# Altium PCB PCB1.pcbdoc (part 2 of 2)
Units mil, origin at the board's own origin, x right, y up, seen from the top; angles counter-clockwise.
Board outline 2441 x 2440.7 mil, 2 copper layers (Top Layer, Bottom Layer), stack 62.2 mil thick; 65 components, 50 nets, 327 pads, 148 vias.
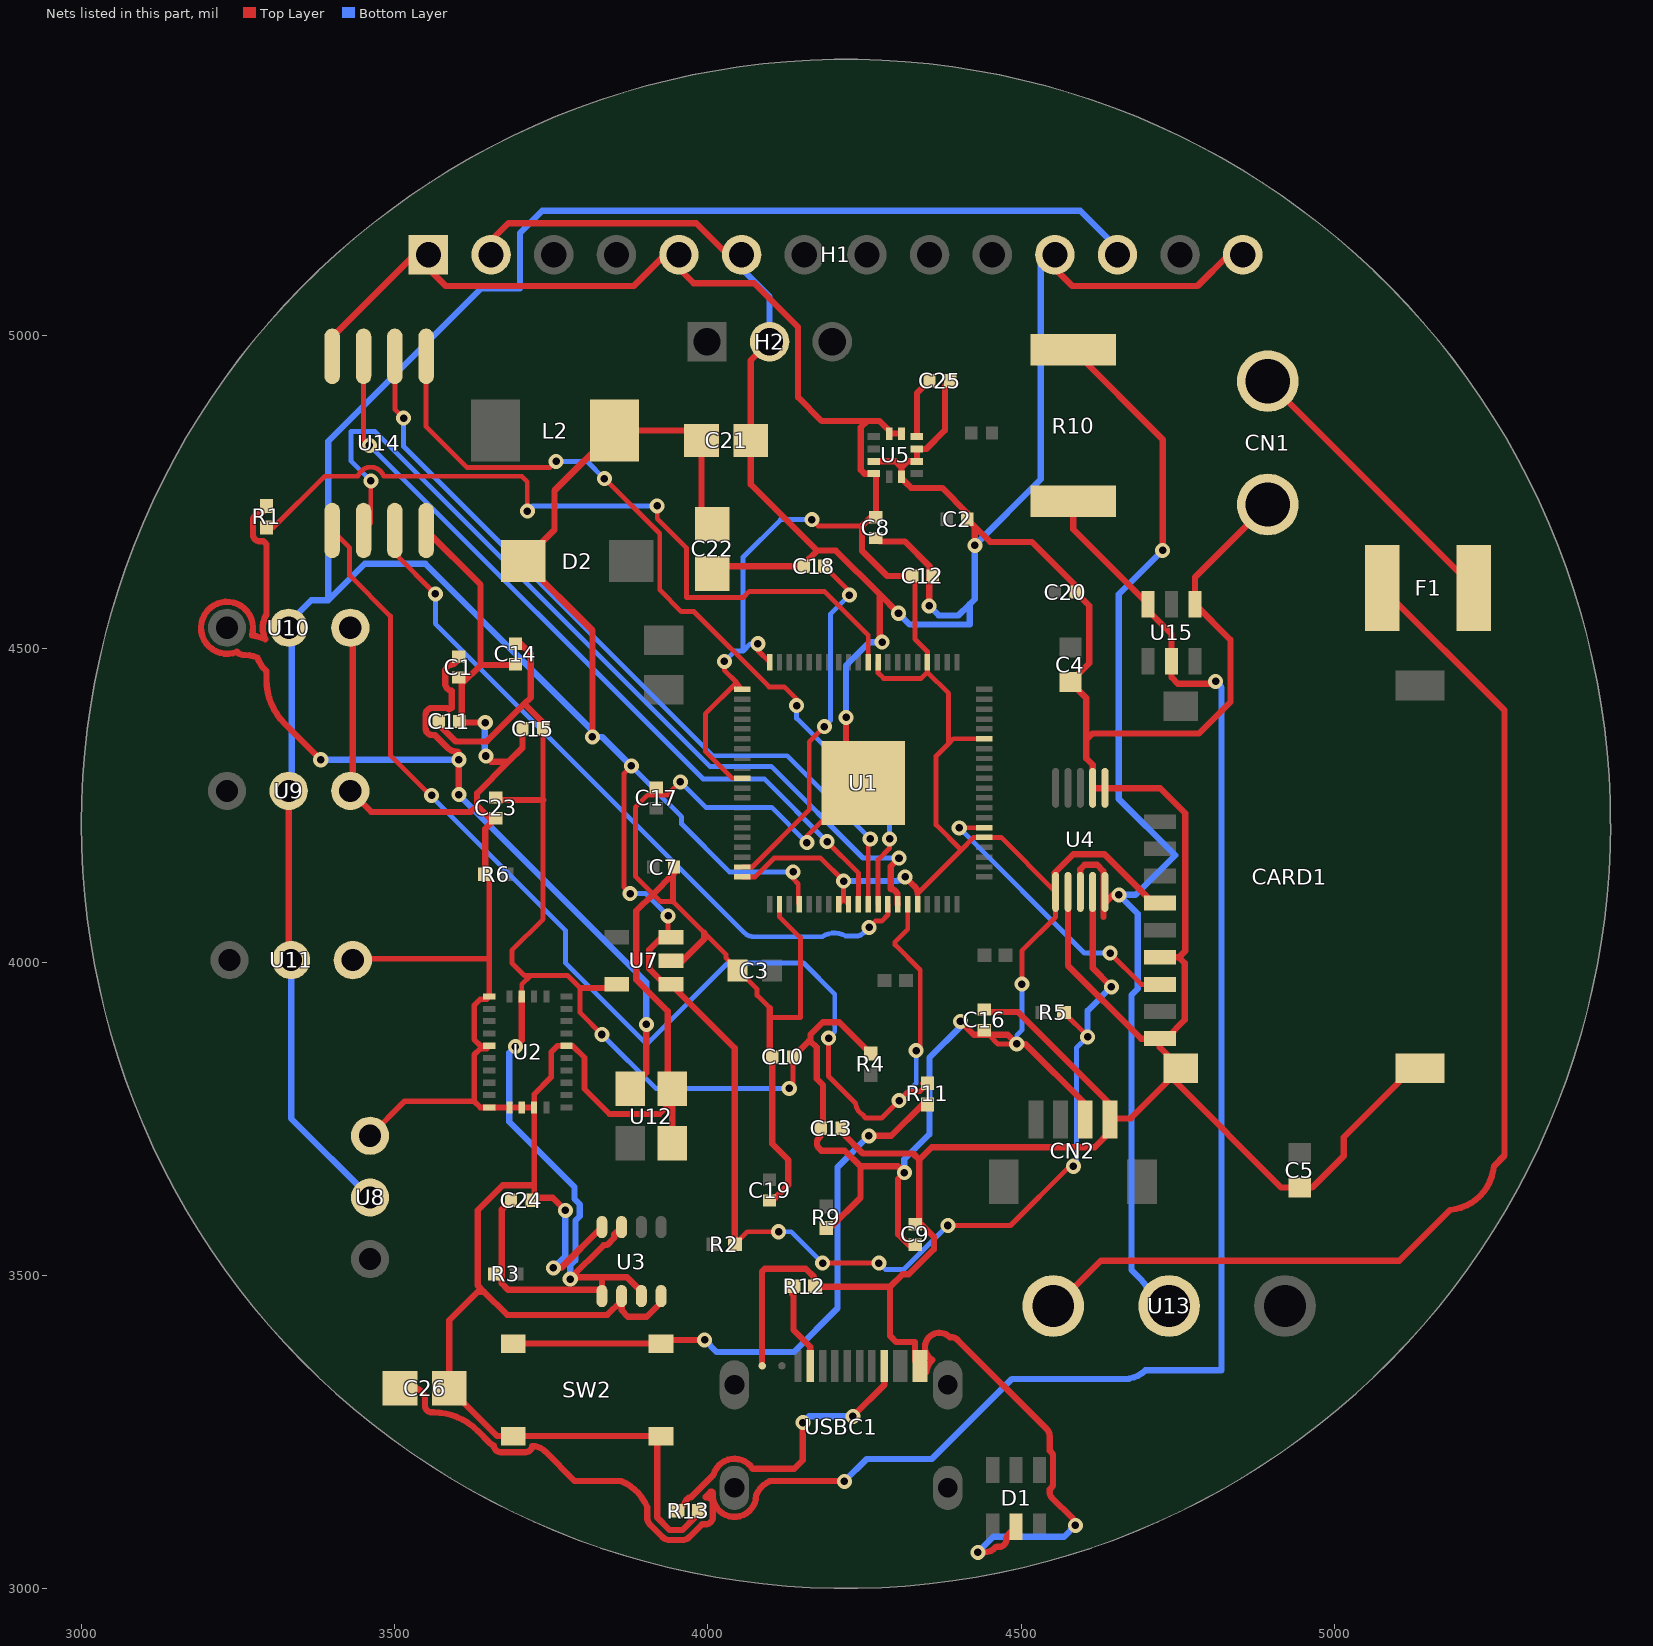
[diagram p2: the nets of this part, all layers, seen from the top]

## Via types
v1: diameter 24, hole 12, Top Layer to Bottom Layer, 148 vias

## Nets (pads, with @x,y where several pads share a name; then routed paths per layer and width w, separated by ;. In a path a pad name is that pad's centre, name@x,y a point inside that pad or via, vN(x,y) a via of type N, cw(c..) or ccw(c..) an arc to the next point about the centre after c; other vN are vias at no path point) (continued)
$1N424: R1.1 U1.30 | length 1256
  Top Layer w7.8: R1.1@3295.4,4693.7 3306.4,4693.7 3388.2,4775.5 3441.3,4775.5 cw(c3461.9,4768.1) 3482.51,4775.52 3703,4775.5 3711.7,4766.8 v1(3711.7,4719.9) ; v1(3919.1,4728.2) 3919.1,4707.6 3966,4660.7 3966,4581.8 4056,4581.8 4066,4591.8 4186,4591.8 4256,4521.8 U1.30@4256,4478.8
  Bottom Layer w7.8: v1(3711.7,4719.9) 3720,4728.2 v1(3919.1,4728.2)
$1N425: C1.1 R1.2 U12.1 | length 1850.3
  Top Layer w10: 3248.1,4495.2 3248.6,4494.7 ccw(c3259.9,4506) 3259.9,4490 3261.9,4490 cw(c3261.9,4444.2) 3280.89,4485.88 ; 3248.15,4495.2 cw(c3232.4,4533.6) 3216.65,4572 cw(c3232.4,4533.6) 3272.07,4521.4 ; 3272.05,4521.33 cw(c3261.9,4444.2) 3293.54,4515.27 ; 3280.84,4485.86 ccw(c3334.7,4506) 3295.34,4464.08 ; 3284.7,4715.8 ccw(c3284.7,4704.8) 3273.7,4704.8 3273.7,4682.6 ccw(c3284.7,4682.6) 3284.7,4671.6 3290,4671.6 ; 3284.7,4715.89 ccw(c3277.2,4734) R1.2@3295.31,4726.5 ; 3290.05,4671.55 cw(c3286.3,4662.5) 3295.35,4666.25 ; 3293.53,4515.34 cw(c3330.8,4533.6) 3295.38,4555.22 3295.4,4666.3 ; 3295.4,4464.1 3295.4,4450.9 ccw(c3395.4,4450.9) 3324.69,4380.19 ; R1.2@3295.4,4726.5 R1.2@3295.4,4727.8 ; 3324.6,4380.2 v1(3382,4322.9) ; 3562.3,4362.3 3560.3,4362.3 cw(c3560.3,4373.3) 3549.3,4373.3 3549.3,4394.6 cw(c3560.3,4394.6) 3560.3,4405.6 3580,4405.6 cw(c3580,4394.6) 3586.7,4403.33 cw(c3593.4,4394.6) 3591.17,4405.37 ; 3562.3,4362.4 cw(c3562.3,4357.6) 3565.69,4360.99 ; 3565.7,4360.9 3585.8,4340.9 ccw(c3597.1,4352.2) 3597.1,4336.2 3599.8,4336.2 ; 3591.15,4433.22 cw(c3591.8,4444.2) 3580.8,4444.2 3580.8,4463.9 cw(c3591.8,4463.9) 3591.8,4474.9 ccw(c3584.3,4493) 3602.41,4485.5 C1.1@3602.4,4487.1 ; 3591.2,4405.4 3591.2,4433.2 ; 3599.78,4336.13 cw(c3597.9,4331.6) v1@3602.43,4333.48 ; v1(3602.4,4267.1) v1@3602.4,4333.5 ; U12.1@3876.1,3797.4 3901.8,3823.1 v1(3901.8,3900.5)
  Bottom Layer w10: v1(3382,4322.9) v1(3602.4,4322.9) ; v1(3602.4,4267.1) 3901.8,3967.8 v1(3901.8,3900.5)
$1N433: C8.1 C9.1 C10.1 C11.1 C12.1 C13.1 C14.1 C15.1 C16.1 C23.1 C24.1 CARD1.4 CN2.2 H1.1 H1.5 R3.2 R4.2 R9.2 U1.5 U1.15 U1.24 U1.29 U1.40 U1.41 U1.50 U1.60 U1.68 U1.69 U1.76 U2.4 U3.2 U3.6 U3.8 U4.6 U5.5 U5.6 U5.10 U7.5 U14.8 | length 8160.8
  Top Layer w7.8: U2.4@3702.8,3945 3702.8,3964.3 3717.1,3978.5 ; C15.1@3737.1,4372.2 3737.1,4258.5 3737.1,4068.5 3687.1,4018.5 3687.1,3998.5 3707.1,3978.5 3717.1,3978.5 ; v1(3830.7,3884.3) 3796,3919 3796,3958.5 3776,3978.5 3717.1,3978.5 ; v1(4026.4,4479.9) 4026.4,4465.9 4046.1,4446.3 ; U1.60@4054.9,4135.9 4075.6,4135.9 4105.6,4165.9 4180,4165.9 v1(4216.6,4129.3) 4216.6,4100.2 ; U1.50@4054.9,4293.4 4038.9,4293.4 3996.1,4336.3 3996.1,4396.3 4046.1,4446.3 ; U1.41@4054.9,4435.2 4046.1,4446.3 ; v1(4080,4508.1) 4080,4497.3 U1.40@4098.5,4478.8 ; v1(4129.9,3798.2) 4136,3804.2 C10.1@4136,3848.5 ; v1(4166.1,4706.3) 4176.1,4696.3 4246.1,4696.3 ; U1.68@4208.7,4092.3 4216.6,4100.2 ; U1.69@4224.5,4092.3 4216.6,4100.2 ; U1.29@4271.7,4478.8 4271.7,4461.5 4280.5,4452.8 4340.5,4452.8 4350.5,4462.8 ; C12.1@4326.1,4616.3 4330.5,4611.8 4330.5,4515.7 4350.5,4495.7 U1.24@4350.5,4478.8 4350.5,4462.8 ; U1.76@4334.7,4092.3 4334.7,4109.3 4404.3,4178.9 ; C16.1@4441,3891.1 4448.3,3883.8 4462.8,3869.2 v1(4493.1,3869.2) ; U1.15@4441.3,4356.4 4391.8,4356.4 4384.3,4348.9 ; v1(4501.3,3964.7) 4501.3,4018 4555.2,4071.9 U4.6@4555.2,4111.9 ; U4.6@4553.2,4113.9 4468.2,4198.9 U1.5@4441.3,4198.9 4424.3,4198.9 4404.3,4178.9 ; 4350.5,4462.8 4384.3,4428.9 4384.3,4348.9 ; 4384.3,4348.9 4364.3,4328.9 4364.3,4218.9 4404.3,4178.9
  Top Layer w8.9: 3796,3958.5 3848.3,3958.5 U7.5@3854.4,3964.7
  Top Layer w9.9: H1.5@3931.6,5129.2 3977.1,5083.6 4074,5083.6 4144,5013.6 4144,4901.7 4182.1,4863.6 4254,4863.6 ; C8.1@4268.2,4710.1 4268.2,4776.2 U5.10@4264.8,4779.6 4250,4779.6 4244,4785.7 4244,4853.6 4254,4863.6 ; U5.5@4309.1,4843.6 U5.6@4289.5,4843.6 4289.5,4848.2 4274,4863.6 4254,4863.6
  Top Layer w10: U14.8@3400.3,4966.9 3400.3,4997.8 3531.6,5129.2 3581.6,5079.2 3881.6,5079.2 H1.5@3931.6,5129.2 ; C11.1@3570.2,4384 3570.2,4379.1 3597.1,4352.2 3647.1,4352.2 3707.1,4412.2 ; R3.2@3660.2,3502.1 3665,3506.9 R3.2@3670.9,3506.9 ; C23.1@3661.5,4262.7 3665.7,4258.5 3737.1,4258.5 ; C24.1@3685.6,3619.7 3670.9,3604.9 R3.2@3670.9,3506.9 ; v1(3692.8,3865) 3702.8,3875 U2.4@3702.8,3945 ; C14.1@3692.8,4508.3 3700.9,4508.3 3717.1,4492.2 3717.1,4422.2 3707.1,4412.2 ; C15.1@3737.1,4372.2 3737.1,4382.2 3707.1,4412.2 ; U3.8@3830.8,3466.7 U3.8@3830.9,3476.9 ; U3.2@3862.3,3576.9 3850.6,3565.2 3850.6,3559.8 3839,3548.2 3833.6,3548.2 3780.3,3494.9 v1(3780.3,3493.9) 3783.3,3496.9 3830.9,3496.9 ; U3.6@3893.8,3466.7 3890.9,3469.5 3890.9,3476.9 3870.9,3496.9 3830.9,3496.9 ; C10.1@4136,3848.5 4161.2,3873.8 4163.7,3873.8 ; 4177.6,3702.5 4181.2,3698.9 4218.6,3698.9 4243.7,3673.8 ; 4177.64,3702.44 cw(c4186.2,3711) 4174.1,3711 4174.1,3711.6 cw(c4184.8,3711.6) 4177.23,3719.17 ccw(c4169.7,3726.7) 4180.4,3726.7 C13.1@4180.4,3734.4 ; C13.1@4183.7,3732.6 4183.7,3803.8 4173.7,3813.8 4173.7,3863.8 4163.7,3873.8 ; R9.2@4189.1,3575.6 4195.6,3575.6 4243.7,3623.8 4243.7,3673.8 ; R4.2@4259.9,3853.8 4209.9,3903.8 4183.7,3903.8 4163.7,3883.8 4163.7,3873.8 ; C8.1@4268.2,4710.1 4259.9,4710.1 4246.1,4696.3 4246.1,4656.3 4286.1,4616.3 C12.1@4326.1,4616.3 ; v1(4315,4135.9) 4329.8,4121.2 ; 4329.81,4121.11 cw(c4318,4109.3) 4334.7,4109.3 ; C9.1@4330.8,3548.5 4320.8,3548.5 4303.7,3565.6 4303.7,3653.8 v1(4313.7,3663.8) 4303.7,3673.8 4243.7,3673.8 ; v1(4403.3,3905.2) 4424.7,3883.8 4448.3,3883.8 4478.6,3883.8 v1(4493.1,3869.2) 4506.9,3869.2 4602.4,3773.7 CN2.2@4602.4,3748.6 ; U4.6@4555.2,4111.9 4553.2,4113.9 4553.2,4141.9 4583.2,4171.9 4633.2,4171.9 4710.9,4094.2 CARD1.4@4721.5,4094.2 ; R3.2@3670.9,3506.9 3670.9,3486.9 3680.9,3476.9 U3.8@3830.9,3476.9 ; U3.8@3830.9,3476.9 3830.9,3496.9
  Bottom Layer w7.8: v1(3830.7,3884.3) 3916.9,3798.2 v1(4129.9,3798.2) ; v1(4026.4,4479.9) 4042.8,4496.3 4056.1,4496.3 ; v1(4080,4508.1) 4067.9,4508.1 4056.1,4496.3 ; v1(4166.1,4706.3) 4116.1,4706.3 4056.1,4646.3 4056.1,4496.3 ; v1(4493.1,3869.2) 4493.1,3883.2 4501.3,3891.3 v1(4501.3,3964.7)
  Bottom Layer w10: v1(3692.8,3865) 3682.8,3855 3682.8,3745 3786.9,3641 3786.9,3621.8 3795.5,3613.1 3795.5,3594 3788.5,3587 3788.5,3524 3780.3,3515.7 v1(3780.3,3493.9) ; v1(4216.6,4129.3) 4299.1,4129.3 ccw(c4299.1,4151.9) v1@4315.08,4135.92 ; v1(4313.7,3663.8) 4313.7,3685 4353.7,3725 4353.7,3847.3 4403.3,3896.8 v1(4403.3,3905.2)
$1N438: R11.1 U1.75 U14.1 | length 2103.8
  Top Layer w7.8: U14.1@3400.3,4688.9 3428,4661.2 3428,4617.5 3493.2,4552.3 3493.2,4330 v1@3558.3,4264.8 ; v1(4192.6,3878.7) 4192.6,3817.7 4236.1,3774.2 ; 4236.13,3774.23 ccw(c4258,3775.3) 4248.81,3755.42 ; 4248.81,3755.43 ccw(c4253.5,3755.7) 4250.18,3752.38 ; 4250.2,3752.3 4251.5,3751 4277.4,3751 v1(4305.4,3778.9) 4319.9,3793.5 4338.7,3793.5 4347.2,3801.9 R11.1@4342.6,3806.5 ; U1.75@4319,4092.3 4319,4052.3 4299,4032.3 4299,4027.3 4339,3987.3 4339,3865.1 v1(4332.6,3858.7)
  Bottom Layer w7.8: v1@3558.3,4264.8 3772.6,4050.5 3772.6,3998.7 3902.4,3868.9 4032.2,3998.7 4152.6,3998.7 4202.6,3948.7 4202.6,3888.7 v1(4192.6,3878.7) ; v1(4305.4,3778.9) 4332.6,3806.2 v1(4332.6,3858.7)
  other v1: 3559.1,4265.9
$1N439: R11.2 SW2.1 SW2.2 | length 967.4
  Top Layer w10: SW2.1@3689.1,3390.9 SW2.2@3925.3,3390.9 3931.1,3396.7 v1(3994.7,3396.7) ; v1(4256.9,3722.5) 4292.6,3722.5 4342.6,3772.4 R11.2@4350.5,3772.4
  Bottom Layer w10: v1(3994.7,3396.7) 4014.1,3377.3 4136.9,3377.3 4206.9,3447.3 4206.9,3672.5 v1(4256.9,3722.5)
$1N444: C18.1 U1.59 | length 576.9
  Top Layer w7.8: U1.59@4054.9,4151.7 4070.6,4151.7 4161.9,4243 4161.9,4351.7 v1(4185.9,4375.7) ; C18.1@4185.9,4632 4225.9,4592 v1(4225.9,4585.7)
  Bottom Layer w7.8: v1(4185.9,4375.7) 4195.9,4385.7 4195.9,4555.7 v1(4225.9,4585.7)
$1N449: U1.74 U14.2 | length 1417.9
  Top Layer w7.8: U14.2@3450.3,4688.9 3461.9,4700.5 v1(3461.9,4768.1)
  Top Layer w10: U1.74@4303.21,4092.41 cw(c4304.2,4093.4) 4302.8,4093.4 4302.8,4105.4 ccw(c4291.8,4105.4) 4291.8,4116.4 4291.8,4152.7 v1(4305.1,4166)
  Bottom Layer w7.8: v1(3461.9,4768.1) 3430.4,4799.6 3430.4,4846.8 3468.7,4846.8 4003.2,4312.3 4101.2,4312.3 4247.6,4166 v1(4305.1,4166)
$1N450: U1.73 U14.3 | length 1134.4
  Top Layer w7.8: U14.3@3500.3,4688.9 3500.3,4652.3 v1(3565,4587.6) ; v1(4257.5,4055.4) 4267.5,4065.4 4277.5,4065.4 4287.5,4075.4 U1.73@4287.5,4092.3
  Bottom Layer w7.8: v1(3565,4587.6) 3565,4540 4058.3,4046.7 ; 4058.27,4046.67 ccw(c4073.4,4061.8) 4073.4,4040.4 4182.3,4040.4 ; 4182.35,4040.4 cw(c4202,4010.6) 4219.74,4041.58 ; 4219.7,4041.6 4238,4041.6 ccw(c4238,4053.8) 4246.63,4045.17 ; 4248.4,4046.3 v1(4257.5,4055.4)
$1N451: U1.72 U14.5 | length 1341
  Top Layer w7.8: U14.5@3550.3,4966.9 3550.3,4854.7 3615.6,4789.3 3747.8,4789.3 v1(3757.8,4799.3) ; v1(3834.7,4771.6) 3835.6,4771.6 3923.1,4684.1 3923.1,4594.1 3957.8,4559.3 3977.8,4559.3 4097.8,4439.3 4121.7,4439.3 4141.7,4419.3 v1(4141.7,4409.3) ; U1.72@4271.7,4092.3 4271.7,4163.5 4290,4181.8 v1(4290,4196.7)
  Bottom Layer w7.8: v1(3757.8,4799.3) 3807,4799.3 v1(3834.7,4771.6) ; v1(4141.7,4409.3) 4141.7,4388.9 4290,4240.6 v1(4290,4196.7)
$1N452: U1.71 U14.6 | length 1259.8
  Top Layer w7.8: U14.6@3500.3,4966.9 3500.3,4882.3 v1(3514.2,4868.4) ; U1.71@4256,4092.3 4256,4193.5 v1(4259.2,4196.7)
  Bottom Layer w7.8: v1(3514.2,4868.4) 3514.2,4823 4007.8,4329.3 4126.5,4329.3 v1(4259.2,4196.7)
$1N453: U1.70 U14.7 | length 1259.2
  Top Layer w7.8: U14.7@3450.3,4966.9 3450.3,4834.2 v1(3459.6,4824.9) ; v1(4190.2,4192.3) 4240.2,4142.3 U1.70@4240.2,4092.3
  Bottom Layer w7.8: v1(3459.6,4824.9) 3992.2,4292.3 4090.2,4292.3 v1(4190.2,4192.3)
$1N456: C25.1 U5.4 | length 97.9
  Top Layer w9.9: U5.4@4333.7,4838.7 4333.7,4908 C25.1@4353.9,4928.2
$1N460: CARD1.7 U1.6 | length 463.9
  Top Layer w7.8: v1(4401.3,4214.3) 4440.9,4214.3 U1.6@4441.3,4214.7 ; v1(4642,4014.3) 4692,3964.3 CARD1.7@4721.5,3964.3
  Bottom Layer w7.8: v1(4401.3,4214.3) 4601.3,4014.3 v1(4642,4014.3)
$1N462: R10.1 U4.8 U4.10 U13.2 | length 1920.6
  Top Layer w10: R10.1@4583.1,4977.2 4726.1,4834.2 v1(4726.1,4657.2) ; U4.8@4594.6,4111.9 4594.6,4148.3 4601.4,4155.1 4621.4,4155.1 4631.4,4145.1 U4.10@4631.4,4115.1 ; 4631.4,4071.9 U4.10@4631.4,4091.9 ; U4.10@4633.9,4111.9 U4.10@4631.4,4115.1 ; v1(4656.1,4107.2) 4646.7,4107.2 U4.10@4631.4,4091.9 ; U4.10@4631.4,4091.9 U4.10@4631.4,4115.1
  Bottom Layer w10: 4691.07,3493.47 cw(c4648.5,3450.9) U13.2@4708.7,3450.9 ; 4691.1,3493.5 4676.1,3508.5 4676.1,3947.2 4686.1,3957.2 4686.1,4077.2 v1(4656.1,4107.2) 4682.8,4107.2 4746,4170.4 4656.1,4260.2 4656.1,4587.2 v1(4726.1,4657.2)
$1N470: C26.1 R10.2 U15.3 U15.5 | length 3163.2
  Top Layer w10: C26.1@3508.4,3319.7 C26.1@3534.6,3319.7 ; C26.1@3534.56,3319.66 cw(c3524.8,3296.1) 3548.36,3305.86 ; 3548.3,3305.9 3548.3,3292.1 ccw(c3559.3,3292.1) 3559.3,3281.1 3561.6,3281.1 cw(c3561.6,3181.1) 3632.31,3251.81 3652.2,3231.9 ccw(c3663.5,3243.2) 3658.32,3228.06 ; 3658.41,3228.12 ccw(c3669.4,3228.5) 3669.4,3217.5 3708.7,3217.5 ccw(c3708.7,3228.5) 3719.63,3227.25 ; 3719.7,3227.3 cw(c3719.7,3198.4) 3740.14,3218.84 ; 3740.1,3218.8 3787.5,3171.4 3861.6,3171.4 cw(c3832.3,3100.7) 3902.98,3129.98 ; 3903.1,3130 3903.1,3113.2 ccw(c3919.1,3113.2) 3907.79,3101.89 ; 3907.7,3101.9 3927.7,3081.9 ; 3927.79,3081.89 ccw(c3939.1,3093.2) 3939.1,3077.2 3959.1,3077.2 ccw(c3959.1,3093.2) 3970.41,3081.89 3990.4,3101.9 ccw(c3979.1,3113.2) 3990.97,3102.47 ; 3990.9,3102.5 3996.8,3102.5 ccw(c3996.8,3113.5) 4007.8,3113.5 4007.8,3134.8 ccw(c3996.8,3134.8) 3996.8,3145.8 ; 3996.4,3146.4 ccw(c3997.4,3146.4) 3996.69,3145.69 ; 3996.5,3146.4 4004.6,3154.6 cw(c4004.6,3150.1) 4007.78,3153.28 4007.8,3148.8 ccw(c4042.4,3148.8) 4077,3148.8 cw(c4115.6,3132.8) 4099.6,3171.42 v1@4216.7,3171.4 ; v1@4216.7,3171.3 cw(c4216.7,3169.6) v1@4217.9,3170.8 ; R10.2@4583.1,4735.8 4583.1,4690.7 U15.3@4702.8,4570.9 4702.8,4560.9 4740.2,4523.5 U15.5@4740.2,4480.5 4740.2,4454.4 4750.2,4444.4 4806.7,4444.4 v1(4810.4,4448)
  Bottom Layer w10: v1(4217.9,3170.9) 4253.7,3206.7 4357.7,3206.7 4485.4,3334.4 4665,3334.4 ; 4665,3334.3 ccw(c4665,3381.6) 4698.45,3348.15 ; 4698.4,3348.2 4820,3348.2 4820,4438.3 v1(4810.4,4448)
$1N473: R12.1 USBC1.A5 | length 141.5
  Top Layer w10: 4134.2,3470.3 R12.1@4136.6,3472.7 ; R12.1@4136.6,3482.4 R12.1@4136.6,3472.7 ; USBC1.A5@4163.5,3355.4 4163.5,3386 4136.6,3412.9 R12.1@4136.6,3472.7
$1N474: F1.1 U13.1 | length 1806.1
  Top Layer w10: U13.1@4561.7,3453.4 4561.7,3457.4 4627.5,3523.2 5103.8,3523.2 5185,3604.3 ; F1.1@5076.8,4597 5271.7,4402.1 5271.7,3691.1 5254.9,3674.2 ; 5184.86,3604.28 ccw(c5178.3,3680.8) 5254.82,3674.24
$1N475: CN1.2 F1.2 | length 466.5
  Top Layer w10: CN1.2@4893.8,4927.3 5222.7,4598.3 F1.2@5222.7,4597
$1N479: R13.1 USBC1.B5 | length 493.2
  Top Layer w10: R13.1@3951.5,3124.1 3963.6,3136.2 cw(c3974.5,3134.8) 3973.1,3145.71 4009,3181.6 ; 4009.04,3181.59 cw(c4042.4,3172.4) 4071.55,3191.04 ; 4071.6,3191.1 4137.8,3191.1 4151.6,3204.8 v1(4151.6,3264.8) ; v1(4231.6,3274.8) 4281.6,3324.8 USBC1.B5@4281.6,3355.4
  Bottom Layer w10: v1(4151.6,3264.8) 4161.6,3274.8 v1(4231.6,3274.8)
$1N485: C21.1 C22.1 D2.1 H1.12 L2.2 R2.2 R5.1 U1.64 U4.9 U7.1 U7.3 U8.2 U9.2 U10.2 U11.2 | length 6797.7
  Top Layer w7.8: v1(3875.8,4109.3) 3865.8,4119.3 3865.8,4300.8 v1(3877.9,4313) ; v1(3936.6,4073.5) 3936.6,4043.9 U7.3@3941,4039.5 ; R2.2@4043.1,3549.4 4063.1,3569.4 v1(4113.1,3569.4) ; v1(4136,4144) 4136,4132.9 4144.2,4124.6 4144.2,4093.9 U1.64@4145.8,4092.3 ; v1(4183.1,3519.4) v1(4273.1,3519.4) ; v1(4383.1,3579.4) 4483.1,3579.4 4577.7,3674 v1(4583.5,3674) ; R5.1@4568.3,3919.4 4606.2,3881.5 v1(4606.2,3880.6)
  Top Layer w10: U9.2@3330.8,4273.2 3330.8,4006.9 U11.2@3334.7,4003 ; v1(3815.8,4359.3) 3815.8,4529.2 D2.1@3705.1,4639.9 3755.1,4689.9 3755.1,4752.7 L2.2@3851,4848.5 3973.9,4848.5 C21.1@3989.8,4832.6 3989.8,4715.8 C22.1@4006.6,4699 ; U7.3@3941,4039.5 3926.3,4039.5 3906.3,4019.5 3906.3,3989.5 3926.3,3969.5 3936.2,3969.5 U7.1@3941,3964.7 4043.1,3862.6 R2.2@4043.1,3549.4 ; U4.9@4614.2,4111.9 4614.2,3990.5 v1(4644.2,3960.5)
  Bottom Layer w7.8: v1(3875.8,4109.3) 3900.7,4109.3 v1(3936.6,4073.5) ; v1(3877.9,4313) 3916.2,4274.6 3916.2,4273.6 3958.1,4231.7 3958.1,4220.3 4034.3,4144 v1(4136,4144) ; v1(4113.1,3569.4) 4133.1,3569.4 v1(4183.1,3519.4) ; v1(4273.1,3519.4) 4283.1,3509.4 4313.1,3509.4 v1(4383.1,3579.4) ; v1(4583.5,3674) 4588.3,3678.8 4588.3,3862.8 v1(4606.2,3880.6)
  Bottom Layer w10: U9.2@3330.8,4273.2 3335.5,4277.9 3335.5,4486 ; U11.2@3334.7,4003 3334.7,3750.1 U8.2@3460.7,3624.1 ; 3335.8,4486.3 3335.8,4546.4 3366.7,4577.4 3393.8,4577.4 ; 3699.9,5076.3 3699.9,5163.5 3735.8,5199.3 4594.5,5199.3 4648.1,5145.7 H1.12@4631.6,5129.2 ; 3700.2,5075.4 3638,5075.4 3393.8,4831.2 3393.8,4577.4 ; v1(3877.9,4313) 3831.5,4359.3 v1(3815.8,4359.3) 3815.8,4369.3 3549.1,4635.9 3452.4,4635.9 3393.8,4577.4 ; v1(4606.2,3880.6) 4606.2,3922.5 v1(4644.2,3960.5)
$1N486: C1.2 C2.2 C3.2 C4.2 C5.2 C7.2 C8.2 C9.2 C10.2 C11.2 C12.2 C13.2 C14.2 C15.2 C16.2 C17.2 C18.2 C19.2 C20.2 C21.2 C22.2 C23.2 C24.2 C25.2 C26.2 CARD1.6 CARD1.9 CARD1.10 CARD1.11 CN1.1 CN2.1 D1.2 H1.2 H1.6 H1.11 H1.14 H2.2 R6.2 R12.2 R13.2 SW2.3 SW2.4 U1.62 U1.81 U2.6 U2.10 U2.15 U2.16 U2.17 U2.18 U2.25 U3.1 U3.5 U3.7 U4.1 U4.2 U4.7 U5.2 U5.3 U5.9 U5.12 U7.2 U8.3 U9.3 U10.3 U11.3 U12.3 U12.4 U14.4 U15.1 USBC1.A1B12 USBC1.B1A12 | length 15195.2
  Top Layer w7.8: C17.2@3917.4,4278.5 3914.2,4275.3 3914.2,4266.8 ; v1(3956,4287.5) 3935.3,4266.8 3914.2,4266.8 ; 4098.7,3915.3 4102.4,3911.5 4147.7,3911.5 4147.7,4038.9 4114.2,4072.3 U1.62@4114.2,4092.3 ; 4098.7,3926.8 4078.7,3946.8 4078.7,3956.8 4028.7,4006.8 4028.7,4012.3 3994.2,4046.8 3944.2,4096.8 3924.2,4096.8 3912.6,4108.5 3884.2,4136.8 3884.2,4246.8 3904.2,4266.8 3914.2,4266.8 ; v1(4158.1,4190.7) 4158.1,4200.7 4245.6,4288.1 U1.81@4248.1,4290.7
  Top Layer w8.9: U11.3@3433.2,4003 3435.1,4005 3651.1,4005 ; U8.3@3460.7,3722.6 3516,3777.8 3626.9,3777.8 ; R6.2@3644.5,4139.9 3651.1,4133.2 3651.1,4005 ; C24.2@3718.7,3619.7 3722.5,3623.6 3722.5,3643.6 U2.18@3722.5,3767.8 ; U12.4@3943,3777.4 3923,3757.4 3843,3757.4 3803,3797.4 3803,3847.4 3784.1,3866.3 U2.25@3774.2,3866.3 3759.9,3866.3 3749.9,3856.3 3749.9,3816.3 3722.5,3788.8 U2.18@3722.5,3767.8 ; 3626.9,3777.8 3636.9,3767.8 U2.15@3651.1,3767.8 U2.16@3683.2,3767.8 U2.17@3702.8,3767.8 U2.18@3722.5,3767.8 ; 3626.9,3777.8 3626.9,3852 3636.9,3862 3646.9,3862 U2.10@3651.1,3866.3 3636.9,3866.3 3626.9,3876.3 3626.9,3930.7 3636.9,3940.7 3646.9,3940.7 U2.6@3651.1,3945 3651.1,4005
  Top Layer w9.9: C21.2@4068.6,4832.6 4068.6,4762.5 4174.3,4656.8 ; U5.9@4264.8,4799.3 4299.3,4799.3 4309.1,4789.5 ; C25.2@4387,4928.2 4378.5,4919.7 4378.5,4849 4348.5,4819 U5.3@4333.7,4819 U5.2@4333.7,4799.3 4318.9,4799.3 4309.1,4789.5 ; C2.2@4414.3,4706.8 4414.3,4716.8 4374.3,4756.8 4324.3,4756.8 4309.1,4771.9 U5.12@4309.1,4774.7 4309.1,4789.5
  Top Layer w10: U10.3@3429.2,4533.6 3433.1,4529.6 3433.1,4282.7 cw(c3419.7,4282.7) U9.3@3429.2,4273.2 3462.8,4239.6 3621.5,4239.6 3631.5,4249.6 ; U14.4@3550.3,4688.9 3637.2,4602 3637.2,4474 ; C1.2@3602.4,4454.1 3607.2,4449.3 3607.2,4444 ; C11.2@3603.2,4384 C11.2@3607.2,4387.9 ; C11.2@3607.2,4384 C11.2@3607.2,4387.9 ; H1.2@3631.6,5129.2 3681.6,5179.2 3981.6,5179.2 H1.6@4031.6,5129.2 ; v1@3643.9,4329.6 3653.9,4319.6 3681.5,4319.6 ; R6.2@3644.5,4139.9 3644.5,4212.6 C23.2@3661.5,4229.6 3651.5,4229.6 3631.5,4249.6 ; v1(3644.6,4382.2) 3612.8,4382.2 C11.2@3607.2,4387.9 ; C14.2@3692.8,4475.3 3691.5,4474 3637.2,4474 ; C15.2@3704,4372.2 3704,4342.2 3681.5,4319.6 ; C24.2@3722.5,3623.6 3752.5,3623.6 v1(3772.5,3603.6) ; 3722.5,3643.6 3672.5,3643.6 3632.5,3603.6 3632.5,3483.6 3642.5,3473.6 ; v1(3753.5,3511.6) 3765.5,3511.6 U3.1@3830.8,3576.9 ; U3.7@3862.3,3466.7 U3.7@3862.3,3459.5 ; SW2.4@3925.3,3243.2 SW2.4@3919.1,3243.2 ; U3.5@3925.3,3466.7 3922.3,3463.7 3922.3,3453.9 3902.3,3433.9 3872.3,3433.9 3862.3,3443.9 U3.7@3862.3,3459.5 ; U7.2@3941,4002.1 3959.5,4002.1 3994.2,4036.8 3994.2,4046.8 ; U12.3@3943,3710.7 3943,3777.4 U12.4@3943,3797.4 3935.8,3804.6 3935.8,3921.7 3885.8,3971.7 3885.8,4081.7 3912.6,4108.5 3944.2,4140.2 ; 3944.2,4096.8 3944.2,4140.2 ; R13.2@3981.7,3124.1 3979.1,3121.5 3979.1,3113.2 3959.1,3093.2 3939.1,3093.2 3919.1,3113.2 SW2.4@3919.1,3243.2 ; C22.2@4006.6,4620.2 4018.4,4632 C18.2@4152.8,4632 4152.8,4635.4 4174.3,4656.8 4204.3,4656.8 4274.3,4586.8 ; C21.2@4068.6,4832.6 4068.6,4960.4 H2.2@4098.5,4990.3 ; USBC1.A1B12@4086.4,3355.7 4086.4,3505.8 4090.9,3510.2 4156.4,3510.2 4169.4,3497.3 4169.4,3481.6 4290.8,3481.6 ; C19.2@4098.5,3619.4 4103.8,3619.4 4128.5,3644.1 4128.5,3684.1 4102.9,3709.7 C10.2@4102.9,3848.5 4098.7,3852.8 4098.7,3915.3 4098.7,3926.8 ; C13.2@4216.6,3743 4216.6,3725.3 4247.5,3694.4 4327.5,3694.4 4337.5,3684.4 ; v1(4220.6,4390.7) 4220.6,4313.1 4245.6,4288.1 U1.81@4248.1,4285.6 ; C8.2@4268.2,4677 4273.8,4671.4 4314.3,4671.4 4354.3,4631.4 4354.3,4611.4 C12.2@4359.1,4616.3 ; v1(4278.1,4510.7) 4274.3,4514.5 4274.3,4586.8 ; v1(4304.3,4556.8) 4274.3,4586.8 ; USBC1.B1A12@4348.6,3345.4 USBC1.B1A12@4338.7,3355.4 4330.8,3363.3 4330.8,3393.3 4300.8,3393.3 4290.8,3403.3 4290.8,3481.6 ; USBC1.B1A12@4348.7,3345.42 cw(c4383,3340.9) 4358.32,3365.15 ; v1(4353.2,4568.4) C12.2@4353.2,4610.3 ; 4358.24,3365.2 cw(c4369.6,3385.2) 4353.08,3369.19 cw(c4369.6,3385.2) 4386.12,3401.21 4387.7,3401.2 cw(c4387.7,3385.2) 4399.01,3396.51 4540.9,3254.5 cw(c4529.6,3243.2) 4545.6,3243.2 4545.6,3219.7 ; C2.2@4414.3,4706.8 4426.1,4695 ; v1(4426.1,4665) 4426.1,4695 ; v1(4431.1,3057.7) 4441.2,3057.7 ccw(c4441.2,3082.2) 4458.52,3064.88 cw(c4462.3,3061.1) 4462.3,3066.5 4465.3,3066.5 ccw(c4465.3,3077.5) 4476.3,3077.5 cw(c4488.8,3077.5) 4479.96,3086.34 ; C16.2@4441,3924.1 4444.7,3920.4 4495,3920.4 4645,3770.4 CN2.1@4645,3750.4 ; 4479.9,3086.3 D1.2@4492.2,3098.6 ; H1.11@4531.6,5129.2 4581.6,5079.2 4781.6,5079.2 H1.14@4831.6,5129.2 ; 4545.6,3158.4 4545.6,3153.5 ccw(c4557.7,3153.5) 4549.14,3144.94 ; 4545.63,3158.49 ccw(c4540.1,3168) 4551.1,3168 4551.1,3210.2 ccw(c4540.1,3210.2) 4545.63,3219.71 ; 4549.1,3144.9 4582.2,3111.9 ; U4.7@4574.9,4111.9 4574.9,3994.3 4691.5,3877.7 CARD1.9@4721.5,3877.7 ; 4582.17,3111.87 cw(c4571,3100.7) v1(4586.8,3100.7) ; CARD1.6@4721.5,4007.6 4752.1,4007.6 ; CARD1.10@4735,3810.4 4675,3750.4 CN2.1@4645,3750.4 ; CARD1.10@4745,3810.4 4915.5,3639.9 C5.2@4945,3639.9 4964.4,3639.9 5015,3690.4 5015,3720.4 5125,3830.4 CARD1.11@5136.9,3830.4 ; CARD1.10@4755,3830.4 4721.5,3863.9 CARD1.9@4721.5,3877.7 ; CN1.1@4893.8,4730.4 4777.6,4614.3 U15.1@4777.6,4570.9 4834.2,4514.3 4834.2,4415 4784.2,4365 4614.2,4365 4604.2,4355 ; C11.2@3607.2,4387.9 3607.2,4444 ; 3607.2,4444 3637.2,4474 ; 3631.5,4249.6 3631.5,4269.6 3681.5,4319.6 ; 3642.5,3473.6 3632.5,3473.6 3587.1,3428.1 C26.2@3587.1,3319.7 3663.5,3243.2 SW2.3@3689.1,3243.2 SW2.4@3919.1,3243.2 ; 3642.5,3473.6 3679.4,3436.7 3839.4,3436.7 U3.7@3862.3,3459.5 ; 3944.2,4140.2 3945.8,4141.7 C7.2@3945.8,4151.7 3944.2,4150.2 3944.2,4140.2 ; 4290.8,3481.6 4310.8,3501.6 4320.8,3501.6 4360.8,3541.6 4360.8,3561.6 4340.8,3581.6 C9.2@4330.8,3581.6 4337.5,3588.4 4337.5,3684.4 ; 4337.5,3684.4 4357.5,3704.4 4617.5,3704.4 4641.8,3728.6 CN2.1@4641.8,3748.6 CN2.1@4645,3750.4 ; 4426.1,4695 4450.5,4670.6 4517,4670.6 4587,4600.6 C20.2@4587,4590.6 4608.8,4568.8 4608.8,4477 C4.2@4578.8,4447 4604.2,4421.5 4604.2,4355 ; 4604.2,4355 4604.2,4325 4614.2,4315 U4.2@4614.2,4278.1 4614.7,4277.6 4722.1,4277.6 4762.1,4237.6 4762.1,4017.6 4752.1,4007.6 ; CARD1.9@4721.5,3877.7 4731.5,3877.7 4761.4,3907.6 4761.4,3998.3 4752.1,4007.6
  Bottom Layer w7.8: v1(3956,4287.5) 3996.7,4246.8 4102,4246.8 v1(4158.1,4190.7)
  Bottom Layer w10: v1@3643.9,4329.6 3643.9,4381.5 v1(3644.6,4382.2) ; v1(3753.5,3511.6) 3772.5,3530.6 v1(3772.5,3603.6) ; H1.6@4031.6,5129.2 4098.5,5062.3 H2.2@4098.5,4990.3 ; v1(4220.6,4390.7) 4220.6,4473.5 4257.7,4510.7 v1(4278.1,4510.7) ; v1(4304.3,4556.8) 4322.4,4538.7 4418.2,4538.7 4418.2,4571.4 ; v1(4353.2,4568.4) 4368.3,4553.3 4400.1,4553.3 4418.2,4571.4 ; v1(4431.1,3057.7) 4455.8,3082.5 4568.7,3082.5 v1(4586.8,3100.7) ; H1.11@4531.6,5129.2 4531.6,4770.5 v1(4426.1,4665) 4426.1,4579.3 4418.2,4571.4
  other v1: 3645.7,4328.9
pads on no net: CARD1.1 CARD1.8 CARD1.12 CARD1.13 CN2.0 U1.3 U1.4 U1.12 U1.13 U1.14 U1.16 U1.17 U1.18 U1.19 U1.20 U1.21 U1.22 U1.23 U1.25 U1.26 U1.27 U1.28 U1.35 U1.36 U1.37 U1.38 U1.39 U1.42 U1.47 U1.48 U1.49 U1.52 U1.53 U1.54 U1.55 U1.56 U1.57 U1.58 U2.1 U2.2 U2.3 U2.5 U2.7 U2.8 U2.9 U2.12 U2.13 U2.14 U2.21 U2.22 U2.23 U2.24 U2.26 U2.27 U2.28 U4.3 U5.7 U5.8 U7.4 U13.3 USBC1.1 USBC1.2 USBC1.3 USBC1.4 USBC1.A8 USBC1.B6 USBC1.B7 USBC1.B8

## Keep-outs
Board Outline Layer:
  region: 3336.2,4841.4 3335.8,4834.5 3334.7,4827.8 3332.7,4821.2 3330.1,4814.9 3326.7,4808.9 3322.7,4803.4 3318,4798.3 3312.8,4793.8 3307.2,4789.9 3301.1,4786.7 3294.7,4784.3 3288.1,4782.5 3281.3,4781.5 3274.5,4781.3 3267.6,4781.9 3260.9,4783.3 3254.4,4785.4 3248.2,4788.3 3242.3,4791.8 3236.9,4796 3231.9,4800.8 3227.6,4806.1 3223.9,4811.8 3220.9,4818 3218.6,4824.4 3217,4831.1 3216.2,4837.9 3216.2,4844.8 3217,4851.6 3218.6,4858.3 3220.9,4864.7 3223.9,4870.9 3227.6,4876.7 3231.9,4882 3236.9,4886.7 3242.3,4890.9 3248.2,4894.5 3254.4,4897.3 3260.9,4899.4 3267.6,4900.8 3274.5,4901.4 3281.3,4901.2 3288.1,4900.2 3294.7,4898.5 3301.1,4896 3307.2,4892.8 3312.8,4888.9 3318,4884.4 3322.7,4879.4 3326.7,4873.8 3330.1,4867.9 3332.7,4861.5 3334.7,4855 3335.8,4848.2
  region: 3336.2,4841.4 3335.8,4834.5 3334.7,4827.8 3332.7,4821.2 3330.1,4814.9 3326.7,4808.9 3322.7,4803.4 3318,4798.3 3312.8,4793.8 3307.2,4789.9 3301.1,4786.7 3294.7,4784.3 3288.1,4782.5 3281.3,4781.5 3274.5,4781.3 3267.6,4781.9 3260.9,4783.3 3254.4,4785.4 3248.2,4788.3 3242.3,4791.8 3236.9,4796 3231.9,4800.8 3227.6,4806.1 3223.9,4811.8 3220.9,4818 3218.6,4824.4 3217,4831.1 3216.2,4837.9 3216.2,4844.8 3217,4851.6 3218.6,4858.3 3220.9,4864.7 3223.9,4870.9 3227.6,4876.7 3231.9,4882 3236.9,4886.7 3242.3,4890.9 3248.2,4894.5 3254.4,4897.3 3260.9,4899.4 3267.6,4900.8 3274.5,4901.4 3281.3,4901.2 3288.1,4900.2 3294.7,4898.5 3301.1,4896 3307.2,4892.8 3312.8,4888.9 3318,4884.4 3322.7,4879.4 3326.7,4873.8 3330.1,4867.9 3332.7,4861.5 3334.7,4855 3335.8,4848.2
  region: 5238,4845 5237.6,4838.1 5236.5,4831.4 5234.5,4824.8 5231.9,4818.5 5228.5,4812.5 5224.5,4807 5219.8,4801.9 5214.7,4797.4 5209,4793.5 5202.9,4790.3 5196.5,4787.9 5189.9,4786.1 5183.1,4785.1 5176.3,4784.9 5169.4,4785.5 5162.7,4786.9 5156.2,4789 5150,4791.9 5144.1,4795.4 5138.7,4799.6 5133.8,4804.4 5129.4,4809.7 5125.7,4815.4 5122.7,4821.6 5120.4,4828.1 5118.8,4834.7 5118,4841.5 5118,4848.4 5118.8,4855.2 5120.4,4861.9 5122.7,4868.3 5125.7,4874.5 5129.4,4880.3 5133.8,4885.6 5138.7,4890.3 5144.1,4894.5 5150,4898.1 5156.2,4900.9 5162.7,4903 5169.4,4904.4 5176.3,4905 5183.1,4904.8 5189.9,4903.8 5196.5,4902.1 5202.9,4899.6 5209,4896.4 5214.7,4892.5 5219.8,4888 5224.5,4883 5228.5,4877.4 5231.9,4871.5 5234.5,4865.1 5236.5,4858.6 5237.6,4851.8
  region: 5238,4845 5237.6,4838.1 5236.5,4831.4 5234.5,4824.8 5231.9,4818.5 5228.5,4812.5 5224.5,4807 5219.8,4801.9 5214.7,4797.4 5209,4793.5 5202.9,4790.3 5196.5,4787.9 5189.9,4786.1 5183.1,4785.1 5176.3,4784.9 5169.4,4785.5 5162.7,4786.9 5156.2,4789 5150,4791.9 5144.1,4795.4 5138.7,4799.6 5133.8,4804.4 5129.4,4809.7 5125.7,4815.4 5122.7,4821.6 5120.4,4828.1 5118.8,4834.7 5118,4841.5 5118,4848.4 5118.8,4855.2 5120.4,4861.9 5122.7,4868.3 5125.7,4874.5 5129.4,4880.3 5133.8,4885.6 5138.7,4890.3 5144.1,4894.5 5150,4898.1 5156.2,4900.9 5162.7,4903 5169.4,4904.4 5176.3,4905 5183.1,4904.8 5189.9,4903.8 5196.5,4902.1 5202.9,4899.6 5209,4896.4 5214.7,4892.5 5219.8,4888 5224.5,4883 5228.5,4877.4 5231.9,4871.5 5234.5,4865.1 5236.5,4858.6 5237.6,4851.8
  region: 3336.6,3677.2 3336.2,3670.4 3335,3663.6 3333.1,3657.1 3330.4,3650.7 3327,3644.8 3323,3639.2 3318.4,3634.2 3313.2,3629.7 3307.5,3625.8 3301.5,3622.6 3295.1,3620.1 3288.5,3618.4 3281.7,3617.4 3274.8,3617.2 3268,3617.8 3261.3,3619.2 3254.8,3621.3 3248.5,3624.1 3242.6,3627.7 3237.2,3631.9 3232.3,3636.6 3228,3641.9 3224.3,3647.7 3221.2,3653.9 3218.9,3660.3 3217.4,3667 3216.6,3673.8 3216.6,3680.7 3217.4,3687.5 3218.9,3694.2 3221.2,3700.6 3224.3,3706.8 3228,3712.5 3232.3,3717.8 3237.2,3722.6 3242.6,3726.8 3248.5,3730.3 3254.8,3733.2 3261.3,3735.3 3268,3736.7 3274.8,3737.3 3281.7,3737.1 3288.5,3736.1 3295.1,3734.3 3301.5,3731.9 3307.5,3728.7 3313.2,3724.8 3318.4,3720.3 3323,3715.2 3327,3709.7 3330.4,3703.7 3333.1,3697.4 3335,3690.8 3336.2,3684.1
  region: 3336.6,3677.2 3336.2,3670.4 3335,3663.6 3333.1,3657.1 3330.4,3650.7 3327,3644.8 3323,3639.2 3318.4,3634.2 3313.2,3629.7 3307.5,3625.8 3301.5,3622.6 3295.1,3620.1 3288.5,3618.4 3281.7,3617.4 3274.8,3617.2 3268,3617.8 3261.3,3619.2 3254.8,3621.3 3248.5,3624.1 3242.6,3627.7 3237.2,3631.9 3232.3,3636.6 3228,3641.9 3224.3,3647.7 3221.2,3653.9 3218.9,3660.3 3217.4,3667 3216.6,3673.8 3216.6,3680.7 3217.4,3687.5 3218.9,3694.2 3221.2,3700.6 3224.3,3706.8 3228,3712.5 3232.3,3717.8 3237.2,3722.6 3242.6,3726.8 3248.5,3730.3 3254.8,3733.2 3261.3,3735.3 3268,3736.7 3274.8,3737.3 3281.7,3737.1 3288.5,3736.1 3295.1,3734.3 3301.5,3731.9 3307.5,3728.7 3313.2,3724.8 3318.4,3720.3 3323,3715.2 3327,3709.7 3330.4,3703.7 3333.1,3697.4 3335,3690.8 3336.2,3684.1
  region: 5238.4,3680.8 5238,3674 5236.8,3667.2 5234.9,3660.7 5232.2,3654.3 5228.9,3648.4 5224.8,3642.8 5220.2,3637.8 5215,3633.3 5209.4,3629.4 5203.3,3626.2 5196.9,3623.7 5190.3,3622 5183.5,3621 5176.6,3620.8 5169.8,3621.4 5163.1,3622.8 5156.6,3624.9 5150.3,3627.7 5144.5,3631.3 5139,3635.5 5134.1,3640.2 5129.8,3645.5 5126.1,3651.3 5123,3657.5 5120.7,3663.9 5119.2,3670.6 5118.4,3677.4 5118.4,3684.3 5119.2,3691.1 5120.7,3697.8 5123,3704.2 5126.1,3710.4 5129.8,3716.1 5134.1,3721.4 5139,3726.2 5144.5,3730.4 5150.3,3733.9 5156.6,3736.8 5163.1,3738.9 5169.8,3740.3 5176.6,3740.9 5183.5,3740.7 5190.3,3739.7 5196.9,3737.9 5203.3,3735.5 5209.4,3732.3 5215,3728.4 5220.2,3723.9 5224.8,3718.8 5228.9,3713.3 5232.2,3707.3 5234.9,3701 5236.8,3694.4 5238,3687.7
  region: 5238.4,3680.8 5238,3674 5236.8,3667.2 5234.9,3660.7 5232.2,3654.3 5228.9,3648.4 5224.8,3642.8 5220.2,3637.8 5215,3633.3 5209.4,3629.4 5203.3,3626.2 5196.9,3623.7 5190.3,3622 5183.5,3621 5176.6,3620.8 5169.8,3621.4 5163.1,3622.8 5156.6,3624.9 5150.3,3627.7 5144.5,3631.3 5139,3635.5 5134.1,3640.2 5129.8,3645.5 5126.1,3651.3 5123,3657.5 5120.7,3663.9 5119.2,3670.6 5118.4,3677.4 5118.4,3684.3 5119.2,3691.1 5120.7,3697.8 5123,3704.2 5126.1,3710.4 5129.8,3716.1 5134.1,3721.4 5139,3726.2 5144.5,3730.4 5150.3,3733.9 5156.6,3736.8 5163.1,3738.9 5169.8,3740.3 5176.6,3740.9 5183.5,3740.7 5190.3,3739.7 5196.9,3737.9 5203.3,3735.5 5209.4,3732.3 5215,3728.4 5220.2,3723.9 5224.8,3718.8 5228.9,3713.3 5232.2,3707.3 5234.9,3701 5236.8,3694.4 5238,3687.7
  lines w0.1: 3216.2,4837.9 3217,4831.1 3218.6,4824.4 3220.9,4818 3223.9,4811.8 3227.6,4806.1 3231.9,4800.8 3236.9,4796 3242.3,4791.8 3248.2,4788.3 3254.4,4785.4 3260.9,4783.3 3267.6,4781.9 3274.5,4781.3 3281.3,4781.5 3288.1,4782.5 3294.7,4784.3 3301.1,4786.7 3307.2,4789.9 3312.8,4793.8 3318,4798.3 3322.7,4803.4 3326.7,4808.9 3330.1,4814.9 3332.7,4821.2 3334.7,4827.8 3335.8,4834.5 3336.2,4841.4 3335.8,4848.2 3334.7,4855 3332.7,4861.5 3330.1,4867.9 3326.7,4873.8 3322.7,4879.4 3318,4884.4 3312.8,4888.9 3307.2,4892.8 3301.1,4896 3294.7,4898.5 3288.1,4900.2 3281.3,4901.2 3274.5,4901.4 3267.6,4900.8 3260.9,4899.4 3254.4,4897.3 3248.2,4894.5 3242.3,4890.9 3236.9,4886.7 3231.9,4882 3227.6,4876.7 3223.9,4870.9 3220.9,4864.7 3218.6,4858.3 3217,4851.6 3216.2,4844.8 3216.2,4837.9 ; 3216.6,3673.8 3217.4,3667 3218.9,3660.3 3221.2,3653.9 3224.3,3647.7 3228,3641.9 3232.3,3636.6 3237.2,3631.9 3242.6,3627.7 3248.5,3624.1 3254.8,3621.3 3261.3,3619.2 3268,3617.8 3274.8,3617.2 3281.7,3617.4 3288.5,3618.4 3295.1,3620.1 3301.5,3622.6 3307.5,3625.8 3313.2,3629.7 3318.4,3634.2 3323,3639.2 3327,3644.8 3330.4,3650.7 3333.1,3657.1 3335,3663.6 3336.2,3670.4 3336.6,3677.2 3336.2,3684.1 3335,3690.8 3333.1,3697.4 3330.4,3703.7 3327,3709.7 3323,3715.2 3318.4,3720.3 3313.2,3724.8 3307.5,3728.7 3301.5,3731.9 3295.1,3734.3 3288.5,3736.1 3281.7,3737.1 3274.8,3737.3 3268,3736.7 3261.3,3735.3 3254.8,3733.2 3248.5,3730.3 3242.6,3726.8 3237.2,3722.6 3232.3,3717.8 3228,3712.5 3224.3,3706.8 3221.2,3700.6 3218.9,3694.2 3217.4,3687.5 3216.6,3680.7 3216.6,3673.8 ; 5118,4841.5 5118.8,4834.7 5120.4,4828.1 5122.7,4821.6 5125.7,4815.4 5129.4,4809.7 5133.8,4804.4 5138.7,4799.6 5144.1,4795.4 5150,4791.9 5156.2,4789 5162.7,4786.9 5169.4,4785.5 5176.3,4784.9 5183.1,4785.1 5189.9,4786.1 5196.5,4787.9 5202.9,4790.3 5209,4793.5 5214.7,4797.4 5219.8,4801.9 5224.5,4807 5228.5,4812.5 5231.9,4818.5 5234.5,4824.8 5236.5,4831.4 5237.6,4838.1 5238,4845 5237.6,4851.8 5236.5,4858.6 5234.5,4865.1 5231.9,4871.5 5228.5,4877.4 5224.5,4883 5219.8,4888 5214.7,4892.5 5209,4896.4 5202.9,4899.6 5196.5,4902.1 5189.9,4903.8 5183.1,4904.8 5176.3,4905 5169.4,4904.4 5162.7,4903 5156.2,4900.9 5150,4898.1 5144.1,4894.5 5138.7,4890.3 5133.8,4885.6 5129.4,4880.3 5125.7,4874.5 5122.7,4868.3 5120.4,4861.9 5118.8,4855.2 5118,4848.4 5118,4841.5 ; 5118.4,3677.4 5119.2,3670.6 5120.7,3663.9 5123,3657.5 5126.1,3651.3 5129.8,3645.5 5134.1,3640.2 5139,3635.5 5144.5,3631.3 5150.3,3627.7 5156.6,3624.9 5163.1,3622.8 5169.8,3621.4 5176.6,3620.8 5183.5,3621 5190.3,3622 5196.9,3623.7 5203.3,3626.2 5209.4,3629.4 5215,3633.3 5220.2,3637.8 5224.8,3642.8 5228.9,3648.4 5232.2,3654.3 5234.9,3660.7 5236.8,3667.2 5238,3674 5238.4,3680.8 5238,3687.7 5236.8,3694.4 5234.9,3701 5232.2,3707.3 5228.9,3713.3 5224.8,3718.8 5220.2,3723.9 5215,3728.4 5209.4,3732.3 5203.3,3735.5 5196.9,3737.9 5190.3,3739.7 5183.5,3740.7 5176.6,3740.9 5169.8,3740.3 5163.1,3738.9 5156.6,3736.8 5150.3,3733.9 5144.5,3730.4 5139,3726.2 5134.1,3721.4 5129.8,3716.1 5126.1,3710.4 5123,3704.2 5120.7,3697.8 5119.2,3691.1 5118.4,3684.3 5118.4,3677.4
  lines w10: 3000,4220.5 3000.4,4189.3 3001.6,4158.2 3003.6,4127 3006.4,4096 3009.9,4065 3014.3,4034.2 3019.5,4003.4 3025.4,3972.8 3032.1,3942.4 3039.6,3912.1 3047.9,3882.1 3056.9,3852.2 3066.7,3822.6 3077.2,3793.3 3088.5,3764.2 3100.5,3735.5 3113.3,3707 3126.7,3678.9 3140.9,3651.2 3155.8,3623.8 3171.4,3596.8 3187.7,3570.2 3204.6,3544 3222.2,3518.3 3240.5,3493 3259.4,3468.3 3278.9,3444 3299,3420.2 3319.8,3396.9 3341.1,3374.2 3363,3352 3385.5,3330.4 3408.5,3309.3 3432,3288.9 3456,3269.1 3480.6,3249.8 3505.6,3231.3 3531.1,3213.3 3557.1,3196.1 3583.4,3179.4 3610.2,3163.5 3637.4,3148.3 3665,3133.7 3692.9,3119.9 3721.2,3106.8 3749.8,3094.4 3778.7,3082.7 3807.9,3071.8 3837.4,3061.7 3867.1,3052.3 3897.1,3043.6 3927.2,3035.8 3957.6,3028.6 3988.1,3022.3 4018.8,3016.8 4049.6,3012 4080.5,3008.1 4111.5,3004.9 4142.6,3002.5 4173.7,3000.9 4204.9,3000.1 4236.1,3000.1 4267.2,3000.9 4298.4,3002.5 4329.4,3004.9 4360.4,3008.1 4391.4,3012 4422.2,3016.8 4452.8,3022.3 4483.4,3028.6 4513.7,3035.8 4543.9,3043.6 4573.8,3052.3 4603.5,3061.7 4633,3071.8 4662.2,3082.7 4691.1,3094.4 4719.7,3106.8 4748,3119.9 4775.9,3133.7 4803.5,3148.3 4830.7,3163.5 4857.5,3179.4 4883.9,3196.1 4909.8,3213.3 4935.3,3231.3 4960.4,3249.8 4984.9,3269.1 5008.9,3288.9 5032.5,3309.3 5055.5,3330.4 5077.9,3352 5099.8,3374.2 5121.2,3396.9 5141.9,3420.2 5162.1,3444 5181.6,3468.3 5200.5,3493 5218.7,3518.3 5236.3,3544 5253.3,3570.2 5269.6,3596.8 5285.1,3623.8 5300,3651.2 5314.2,3678.9 5327.7,3707 5340.4,3735.5 5352.5,3764.2 5363.7,3793.3 5374.3,3822.6 5384.1,3852.2 5393.1,3882.1 5401.4,3912.1 5408.8,3942.4 5415.6,3972.8 5421.5,4003.4 5426.6,4034.2 5431,4065 5434.6,4096 5437.4,4127 5439.4,4158.2 5440.5,4189.3 5440.9,4220.5 5440.5,4251.6 5439.4,4282.8 5437.4,4313.9 5434.6,4344.9 5431,4375.9 5426.6,4406.8 5421.5,4437.5 5415.6,4468.1 5408.8,4498.6 5401.4,4528.8 5393.1,4558.9 5384.1,4588.7 5374.3,4618.3 5363.7,4647.6 5352.5,4676.7 5340.4,4705.5 5327.7,4733.9 5314.2,4762 5300,4789.8 5285.1,4817.2 5269.6,4844.2 5253.3,4870.7 5236.3,4896.9 5218.7,4922.6 5200.5,4947.9 5181.6,4972.7 5162.1,4997 5141.9,5020.8 5121.2,5044.1 5099.8,5066.8 5077.9,5089 5055.5,5110.6 5032.5,5131.6 5008.9,5152.1 4984.9,5171.9 4960.4,5191.1 4935.3,5209.7 4909.8,5227.6 4883.9,5244.9 4857.5,5261.5 4830.7,5277.4 4803.5,5292.7 4775.9,5307.2 4748,5321 4719.7,5334.2 4691.1,5346.5 4662.2,5358.2 4633,5369.1 4603.5,5379.3 4573.8,5388.7 4543.9,5397.3 4513.7,5405.2 4483.4,5412.3 4452.8,5418.6 4422.2,5424.2 4391.4,5428.9 4360.4,5432.9 4329.4,5436.1 4298.4,5438.5 4267.2,5440 4236.1,5440.8 4204.9,5440.8 4173.7,5440 4142.6,5438.5 4111.5,5436.1 4080.5,5432.9 4049.6,5428.9 4018.8,5424.2 3988.1,5418.6 3957.6,5412.3 3927.2,5405.2 3897.1,5397.3 3867.1,5388.7 3837.4,5379.3 3807.9,5369.1 3778.7,5358.2 3749.8,5346.5 3721.2,5334.2 3692.9,5321 3665,5307.2 3637.4,5292.7 3610.2,5277.4 3583.4,5261.5 3557.1,5244.9 3531.1,5227.6 3505.6,5209.7 3480.6,5191.1 3456,5171.9 3432,5152.1 3408.5,5131.6 3385.5,5110.6 3363,5089 3341.1,5066.8 3319.8,5044.1 3299,5020.8 3278.9,4997 3259.4,4972.7 3240.5,4947.9 3222.2,4922.6 3204.6,4896.9 3187.7,4870.7 3171.4,4844.2 3155.8,4817.2 3140.9,4789.8 3126.7,4762 3113.3,4733.9 3100.5,4705.5 3088.5,4676.7 3077.2,4647.6 3066.7,4618.3 3056.9,4588.7 3047.9,4558.9 3039.6,4528.8 3032.1,4498.6 3025.4,4468.1 3019.5,4437.5 3014.3,4406.8 3009.9,4375.9 3006.4,4344.9 3003.6,4313.9 3001.6,4282.8 3000.4,4251.6 3000,4220.5

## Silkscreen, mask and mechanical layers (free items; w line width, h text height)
Top Silkscreen Layer:
  drawing of 308 lines, arcs and shapes, not listed
  text "GTR70E WYVERN" at 3673.3,5198.9 h98.4
Bottom Silkscreen Layer:
  drawing of 308 lines, arcs and shapes, not listed
  text "GTR70E WYVERN" at 4665.4,5198.9 h118.1
Mechanical Layer:
  drawing of 220 lines, arcs and shapes, not listed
